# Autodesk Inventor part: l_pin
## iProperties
Author: GJOHNST2
Shininess: 20.0
Length Units: 11272
Angle Units: 11286
Time Units: 11279
Mass Units: 11290
Length Display Precision: 3
Angle Display Precision: 2
Compacted: True
PropertySet Name: _Private Model Information
Created: 2001-12
Part Number: l_pin
Document SubType Name: Modeling
Designer: GJOHNST2
Control State: 0
Master: False
Checked Out: False
PropertySet Name: Design Tracking Control
Density: 0.0
Volumn: 0.0
Area: 0.0
PropertySet Name: Model Information
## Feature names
1. Extrusion1
2. Extrusion2
3. Fillet1
4. Extrusion3
5. Fillet2
